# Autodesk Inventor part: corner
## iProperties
Created: 2008-04
Part Number: corner
Document SubType Name: Modeling
Designer: Jayson Martinez
Density: 1 g/cm^3
Author: Jayson Martinez
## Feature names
1. Extrusion1
